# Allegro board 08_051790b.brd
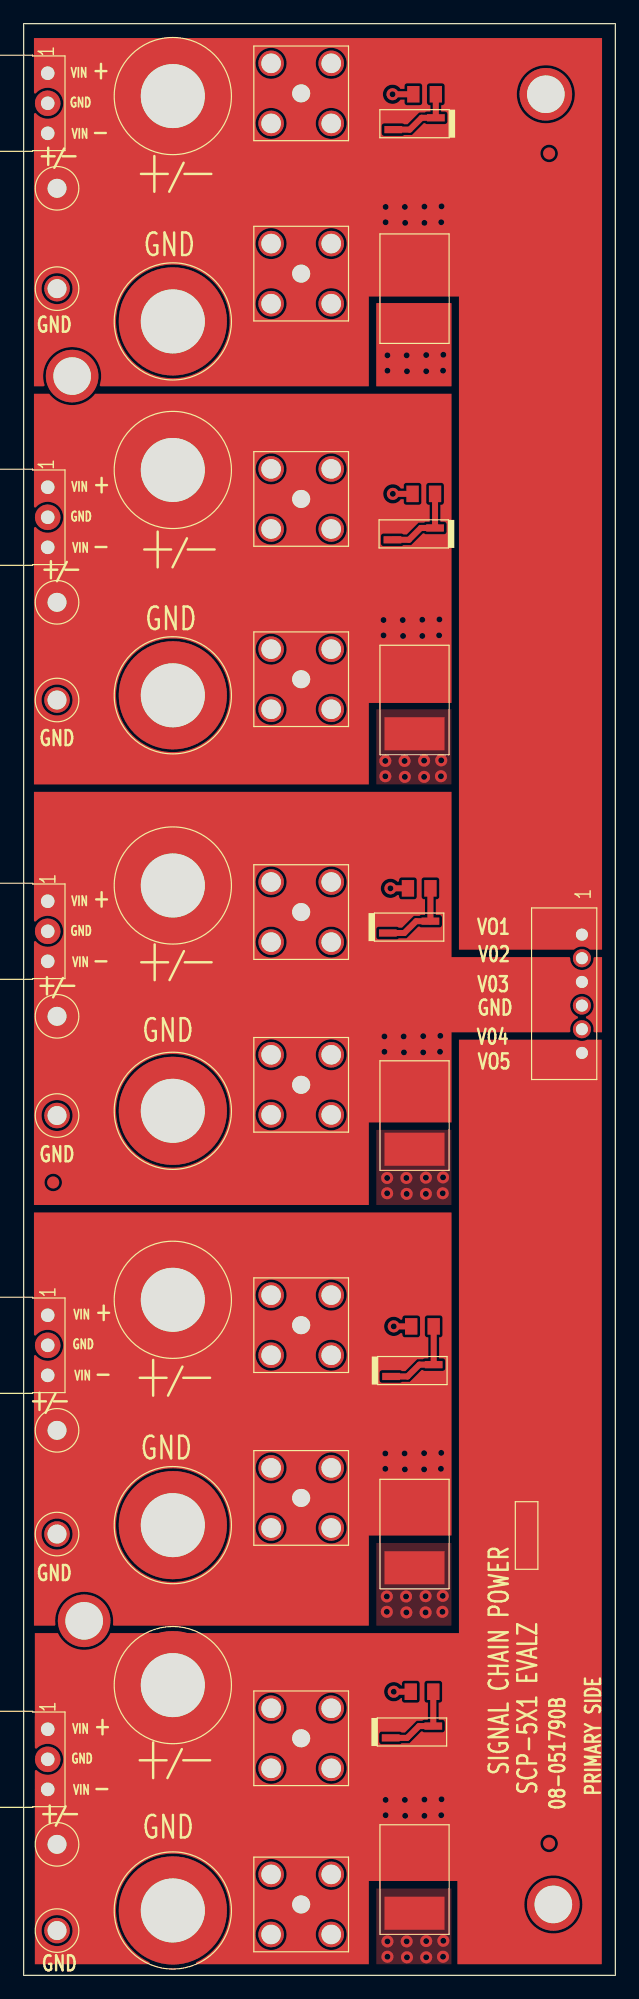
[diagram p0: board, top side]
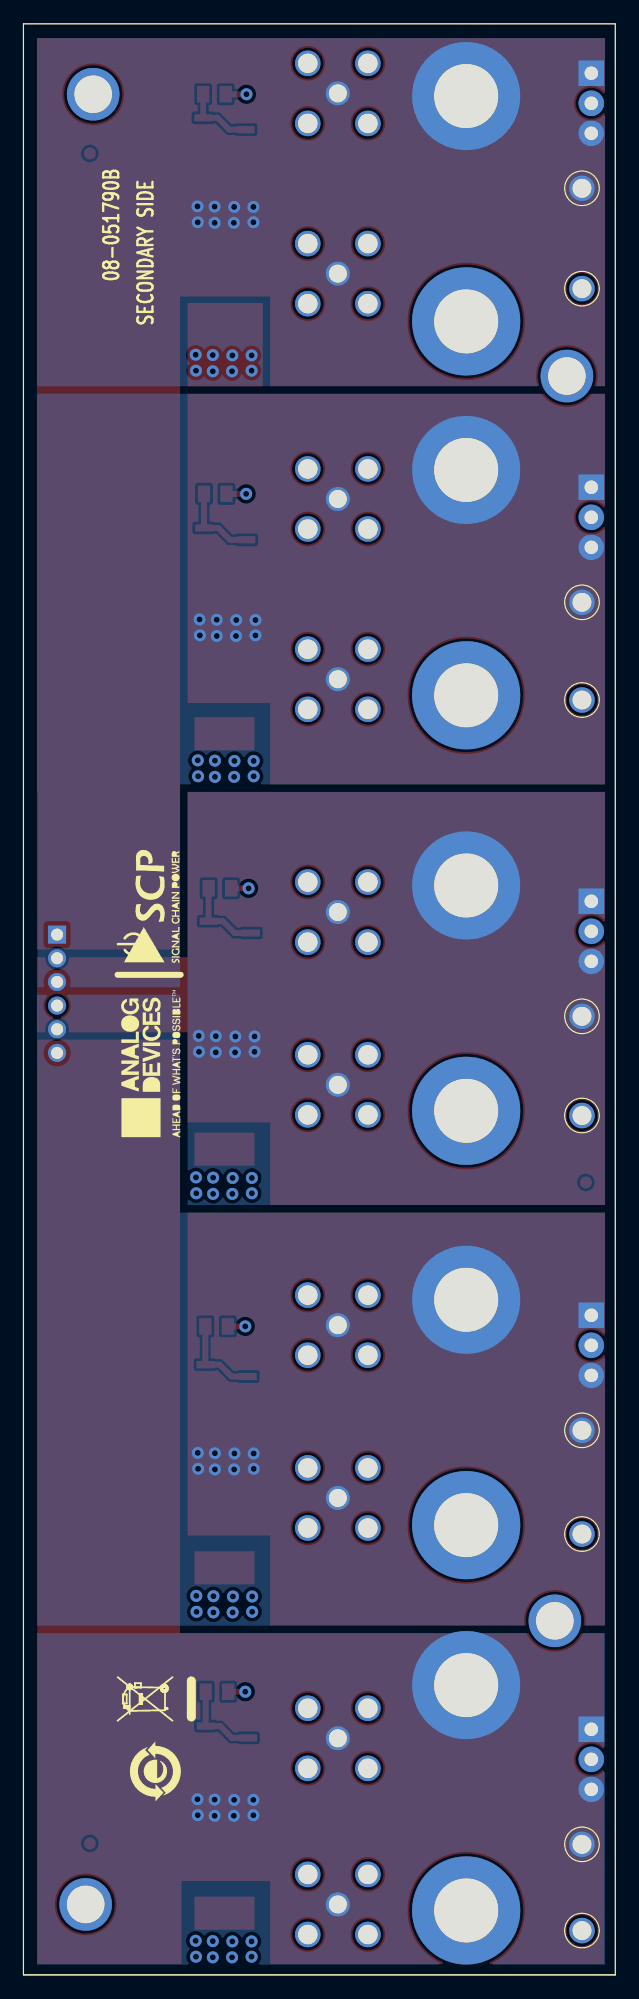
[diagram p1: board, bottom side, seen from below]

Outline 50 x 165 mm; copper layers: TOP, L2_GND, L3_GND, BOTTOM. Coordinates in mm from the lower left corner of the outline.
Outline path: 0,165 0,0 50,0 50,165 0,165

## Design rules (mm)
constraint set DEFAULT: min track width 0.203

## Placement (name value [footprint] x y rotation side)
C1  10UF  [C2220-1]  33.03 142.6 270 top
C2  10UF  [C2220-1]  33.03 107.82 270 top
C3  10UF  [C2220-1]  33.03 72.69 270 top
C4  10UF  [C2220-1]  33.03 37.31 270 top
C5  10UF  [C2220-1]  33.03 8.1 270 top
INPUT1  PBC03SBAN  [CNTHMHDRRA1X3L300W100H145]  2.03 160.81 270 top
INPUT2  PBC03SBAN  [CNTHMHDRRA1X3L300W100H145]  2.03 125.81 270 top
INPUT3  PBC03SBAN  [CNTHMHDRRA1X3L300W100H145]  2.03 90.81 270 top
INPUT4  PBC03SBAN  [CNTHMHDRRA1X3L300W100H145]  2.03 55.8 270 top
INPUT5  PBC03SBAN  [CNTHMHDRRA1X3L300W100H145]  2.03 20.8 270 top
J1  575-4  [CNBANANAD312LD203]  12.6 158.88 0 top
J2  575-4  [CNBANANAD312LD203]  12.6 139.83 0 top
J3  575-4  [CNBANANAD312LD203]  12.6 127.27 0 top
J4  575-4  [CNBANANAD312LD203]  12.6 108.22 0 top
J5  575-4  [CNBANANAD312LD203]  12.6 92.14 0 top
J6  575-4  [CNBANANAD312LD203]  12.6 73.09 0 top
J7  575-4  [CNBANANAD312LD203]  12.6 57.11 0 top
J8  575-4  [CNBANANAD312LD203]  12.6 38.06 0 top
J9  575-4  [CNBANANAD312LD203]  12.6 24.54 0 top
J10  575-4  [CNBANANAD312LD203]  12.6 5.49 0 top
LED1  LTST-C235KGKRKT  [LED1206_4P]  33.03 156.54 180 top
LED2  LTST-C235KGKRKT  [LED1206_4P]  32.96 121.86 180 top
LED3  LTST-C235KGKRKT  [LED1206_4P]  32.57 88.62 0 top
LED4  LTST-C235KGKRKT  [LED1206_4P]  32.85 51.13 0 top
LED5  LTST-C235KGKRKT  [LED1206_4P]  32.82 20.57 0 top
NOREF  -  []  0 165 0 top
NOREF#2  -  []  0 164.97 270 top
NOREF#3  -  [unnamed#2]  44.13 159.03 0 top
NOREF#4  -  []  0 165 0 top
NOREF#5  -  []  2.03 160.81 0 top
NOREF#6  -  [unnamed#2]  44.41 154.03 0 top
NOREF#7  -  [unnamed#2]  44.76 5.99 0 top
NOREF#8  -  []  -116.1 331.09 0 top
NOREF#9  -  []  0 0.02 0 top
NOREF#10  -  []  0 0 0 top
NOREF#11  -  []  50 165 0 top
NOREF#12  -  []  50 164.97 180 top
NOREF#13  -  []  -248.05 234.9 0 top
NOREF#14  -  []  130.27 193.05 0 top
NOREF#15  -  []  -172 -51.33 0 top
NOREF#16  -  []  25.59 187.4 0 top
NOREF#17  -  [unnamed#2]  44.41 11.15 0 top
NOREF#18  -  []  50 0 90 top
NOREF#19  -  []  -137.33 279.5 0 top
NOREF#20  -  []  2.03 160.81 0 top
NOREF#21  -  [unnamed#2]  2.5 67.03 0 top
NOREF#22  -  []  50 0.03 90 top
NOREF#23  -  []  0 0 0 top
NOREF#24  -  []  0 0 0 top
NOREF#25  -  []  -172.76 -53.49 0 top
NOREF#26  -  [unnamed#2]  5.11 29.97 0 top
NOREF#27  -  []  -111.58 106.27 0 top
NOREF#28  -  [unnamed#2]  4.1 135.2 0 top
NOREF#29  -  []  -170.61 -51.97 0 top
NOREF#30  -  []  38.87 17.25 90 bottom
NOREF#31  -  []  -27.91 92.79 90 bottom
NOREF#32  -  []  35.52 23.17 90 bottom
NOREF#33  -  []  -28.21 79.04 90 bottom
NOREF#34  -  []  39.23 76.77 90 bottom
NOREF#35  -  []  39.48 90.4 90 bottom
P6  DF3A-6P-2DSA  [CNTHMHDR1X6L551W197H209]  47.18 87.99 270 top
R1  TBD0805  [R0805]  33.88 159.03 180 top
R2  TBD0805  [R0805]  33.81 125.25 180 top
R3  TBD0805  [R0805]  33.42 91.9 180 top
R4  TBD0805  [R0805]  33.7 54.86 180 top
R5  TBD0805  [R0805]  33.67 23.98 180 top
SMA1  5-1814832-1  [CNTYCO1814832]  23.45 159.11 0 top
SMA2  5-1814832-1  [CNTYCO1814832]  23.45 143.87 0 top
SMA3  5-1814832-1  [CNTYCO1814832]  23.45 124.82 0 top
SMA4  5-1814832-1  [CNTYCO1814832]  23.45 109.58 0 top
SMA5  5-1814832-1  [CNTYCO1814832]  23.45 89.89 0 top
SMA6  5-1814832-1  [CNTYCO1814832]  23.45 75.29 0 top
SMA7  5-1814832-1  [CNTYCO1814832]  23.45 54.97 0 top
SMA8  5-1814832-1  [CNTYCO1814832]  23.45 40.36 0 top
SMA9  5-1814832-1  [CNTYCO1814832]  23.45 20.04 0 top
SMA10  5-1814832-1  [CNTYCO1814832]  23.45 5.99 0 top
TP1  RED  [CNKEY5XXXTP]  2.82 151.08 0 top
TP2  BLK  [CNKEY5XXXTP]  2.82 142.6 0 top
TP3  RED  [CNKEY5XXXTP]  2.82 116.08 0 top
TP4  BLK  [CNKEY5XXXTP]  2.82 107.82 0 top
TP5  RED  [CNKEY5XXXTP]  2.82 81.08 0 top
TP6  BLK  [CNKEY5XXXTP]  2.82 72.69 0 top
TP7  RED  [CNKEY5XXXTP]  2.82 46.08 0 top
TP8  BLK  [CNKEY5XXXTP]  2.82 37.31 0 top
TP9  RED  [CNKEY5XXXTP]  2.82 11.07 0 top
TP10  BLK  [CNKEY5XXXTP]  2.82 3.78 0 top

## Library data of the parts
C1-C5 = CAP: Tolerance: 10; User Part Number: UPN; alternate symbols: (); part number: CAP_SM-10UF,50V,10,E007065,C2220-1; tolerance: 10
INPUT1-INPUT5 = CN3P: Tolerance: N/A; User Part Number: UPN; alternate symbols: (CNTHMHDRRA1X3L300W100H145_SCP); part number: CN3P_TH-PBC03SBAN,E034137,CNTHMHDRRA1X3L300W100H145; tolerance: N/A
J1-J10 = CNTP1P: Tolerance: N/A; User Part Number: UPN; alternate symbols: (); part number: CNTP1P_TH-575-4,E012555,CNBANANAD312LD203; tolerance: N/A
LED1-LED5 = DIOLED_4P_V21: User Part Number: UPN; Tolerance: N/A; alternate symbols: (LED1206_4P_67BRDTHK); part number: DIOLED_4P_V21_SM-LTST-C235KGKRKT,2V,N/A,E034174,LED1206_4P; tolerance: N/A
P6 = CN6P: User Part Number: UPN; Tolerance: N/A; alternate symbols: (); part number: CN6P_TH-DF3A-6P-2DSA,E033743,CNTHMHDR1X6L551W197H209; tolerance: N/A
R1-R5 = RES: User Part Number: UPN; alternate symbols: (R0805L); part number: RES_SM-TBD0805,E004051,TBD0805,TBD0805,R0805
SMA1-SMA10 = CNBNC5P: Tolerance: N/A; User Part Number: UPN; alternate symbols: (); part number: CNBNC5P_TH-5-1814832-1,E010606,CNTYCO1814832; tolerance: N/A
TP1 TP3 TP5 TP7 TP9 = CNTP1P: Tolerance: N/A; User Part Number: UPN; alternate symbols: (); part number: CNTP1P_TH-RED,E023025,CNKEY5XXXTP; tolerance: N/A
TP2 TP4 TP6 TP8 TP10 = CNTP1P: Tolerance: N/A; User Part Number: UPN; alternate symbols: (); part number: CNTP1P_TH-BLK,E022843,CNKEY5XXXTP; tolerance: N/A

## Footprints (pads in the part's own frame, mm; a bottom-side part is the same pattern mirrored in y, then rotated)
C2220-1
  rect 2.794x5.08 smd: 1(-2.85,0) 2(2.85,0)
CNBANANAD312LD203
  round 9.144 hole 5.41: 1(0,0)
CNKEY5XXXTP
  round 2.159 hole 1.6: 1(0,0)
CNTHMHDR1X6L551W197H209
  rect 1.524x1.524 hole 1.016: 1(0,0)
  round 1.524 hole 1.016: 2(2,0) 3(4,0) 4(6,0) 5(8,0) 6(10,0)
CNTHMHDRRA1X3L300W100H145
  rect 2.159x2.159 hole 1.143: 1(0,0)
  round 2.159 hole 1.143: 2(2.54,0) 3(5.08,0)
CNTYCO1814832
  round 2.032 hole 1.524: 1(0,0)
  round 2.159 hole 1.651: 2(-2.54,2.54) 3(2.54,2.54) 4(2.54,-2.54) 5(-2.54,-2.54)
LED1206_4P
  rect 1.499x0.61 smd: 1(-1.8,-0.5) 2(1.8,-0.5) 3(1.8,0.5) 4(-1.8,0.5)
R0805
  rect 1.041x1.397 smd: 1(-0.95,0) 2(0.95,0)
unnamed#2
  round 4.445 hole 3.175 unplated: (0,0)

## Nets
AGND: C1.2(N2) C2.2(N2) C3.2(N2) C4.2(N2) C5.2(N2) INPUT1.2 INPUT2.2 INPUT3.2 INPUT4.2 INPUT5.2 J2.1(N1) J4.1(N1) J6.1(N1) J8.1(N1) J10.1(N1) P6.4 R1.2(N2) R2.2(N2) R3.2(N2) R4.2(N2) R5.2(N2) SMA1.2 SMA1.3 SMA1.4 SMA1.5(SH4) SMA2.2 SMA2.3 SMA2.4 SMA2.5(SH4) SMA3.2 SMA3.3 SMA3.4 SMA3.5(SH4) SMA4.2 SMA4.3 SMA4.4 SMA4.5(SH4) SMA5.2 SMA5.3 SMA5.4 SMA5.5(SH4) SMA6.2 SMA6.3 SMA6.4 SMA6.5(SH4) SMA7.2 SMA7.3 SMA7.4 SMA7.5(SH4) SMA8.2 SMA8.3 SMA8.4 SMA8.5(SH4) SMA9.2 SMA9.3 SMA9.4 SMA9.5(SH4) SMA10.2 SMA10.3 SMA10.4 SMA10.5(SH4) TP2.1(N1) TP4.1(N1) TP6.1(N1) TP8.1(N1) TP10.1(N1)
OUTPUT1: C1.1 INPUT1.1 INPUT1.3(N3) J1.1(N1) LED1.2 LED1.4(C2) P6.1 SMA1.1 SMA2.1 TP1.1(N1)
OUTPUT2: C2.1 INPUT2.1 INPUT2.3(N3) J3.1(N1) LED2.2 LED2.4(C2) P6.2 SMA3.1 SMA4.1 TP3.1(N1)
OUTPUT3: C3.1 INPUT3.1 INPUT3.3(N3) J5.1(N1) LED3.2 LED3.4(C2) P6.3 SMA5.1 SMA6.1 TP5.1(N1)
OUTPUT4: C4.1 INPUT4.1 INPUT4.3(N3) J7.1(N1) LED4.2 LED4.4(C2) P6.5 SMA7.1 SMA8.1 TP7.1(N1)
OUTPUT5: C5.1 INPUT5.1 INPUT5.3(N3) J9.1(N1) LED5.2 LED5.4(C2) P6.6(N6) SMA9.1 SMA10.1 TP9.1(N1)
UNNAMED_2_DIOLED4PV21_I36_A2: LED5.1 LED5.3 R5.1
UNNAMED_2_DIOLED4PV21_I37_A2: LED4.1 LED4.3 R4.1
UNNAMED_2_DIOLED4PV21_I54_A2: LED2.1 LED2.3 R2.1
UNNAMED_2_DIOLED4PV21_I55_A2: LED1.1 LED1.3 R1.1
UNNAMED_2_DIOLED4PV21_I57_A2: LED3.1 LED3.3 R3.1

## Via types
v1: diameter 1.016, hole 0.508, TOP to BOTTOM, 85 vias

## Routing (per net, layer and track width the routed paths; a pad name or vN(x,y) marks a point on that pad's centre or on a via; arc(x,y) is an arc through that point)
AGND: length 7.8
  TOP w0.508: R3.2 v1(30.99,91.9) ; R2.2 v1(31.2,125.25) ; R5.2 v1(31.27,23.98) ; R4.2 v1(31.27,54.86) ; R1.2 v1(31.17,159.03)
  vias: v1(30.56,102.67) v1(30.56,101.37) v1(30.74,136.96) v1(30.74,135.66) v1(30.71,67.41) v1(30.71,66.12) v1(30.69,32.03) v1(30.69,30.73) v1(30.74,2.87) v1(30.74,1.57) v1(32.19,102.67) v1(32.21,101.32) v1(32.37,136.96) v1(32.34,67.41) v1(32.37,66.07) v1(32.32,32.03) v1(32.34,30.68) v1(32.37,2.87) v1(32.39,135.61) v1(32.39,1.52) v1(33.84,102.69) v1(33.84,101.32) v1(33.97,32.05) v1(33.97,30.68) v1(34.02,136.98) v1(34.02,135.61) v1(33.99,67.44) v1(33.99,66.07) v1(34.02,2.9) v1(34.02,1.52) v1(35.26,101.37) v1(35.29,102.72) v1(35.46,137.01) v1(35.44,135.66) v1(35.44,67.46) v1(35.41,66.12) v1(35.41,32.08) v1(35.39,30.73) v1(35.46,2.92) v1(35.44,1.57)
OUTPUT1:
  vias: v1(30.59,149.5) v1(30.59,148.21) v1(32.21,149.5) v1(32.24,148.16) v1(33.86,149.53) v1(33.86,148.16) v1(35.31,149.56) v1(35.29,148.21)
OUTPUT2: length 0
  vias: v1(30.41,114.58) v1(30.41,113.28) v1(32.04,114.58) v1(32.06,113.23) v1(33.69,114.6) v1(33.69,113.23) v1(35.13,114.63) v1(35.11,113.28)
OUTPUT3:
  vias: v1(30.49,79.38) v1(30.49,78.08) v1(32.11,79.38) v1(32.14,78.03) v1(33.76,79.4) v1(33.76,78.03) v1(35.21,79.43) v1(35.19,78.08)
OUTPUT4:
  vias: v1(30.56,44.12) v1(30.56,42.82) v1(32.19,44.12) v1(32.21,42.77) v1(33.84,44.15) v1(33.84,42.77) v1(35.26,42.82) v1(35.29,44.17)
OUTPUT5: length 2.9
  TOP w0.203: 21.04,28.14 22.46,28.14 23.48,27.13
  vias: v1(30.59,14.83) v1(30.59,13.54) v1(32.21,14.83) v1(32.24,13.49) v1(33.86,14.86) v1(33.86,13.49) v1(35.31,14.88) v1(35.29,13.54)
UNNAMED_2_DIOLED4PV21_I36_A2: length 6.9
  TOP w0.508: LED5.1 32.41,20.07 33.41,21.07 LED5.3 R5.1
UNNAMED_2_DIOLED4PV21_I37_A2: length 7.2
  TOP w0.508: R4.1 LED4.3 33.44,51.63 32.44,50.63 LED4.1
UNNAMED_2_DIOLED4PV21_I54_A2: length 6.9
  TOP w0.508: R2.1 LED2.1 33.56,122.36 32.56,121.36 LED2.3
UNNAMED_2_DIOLED4PV21_I55_A2: length 6
  TOP w0.508: R1.1 LED1.1 33.62,157.04 32.62,156.04 LED1.3
UNNAMED_2_DIOLED4PV21_I57_A2: length 6.8
  TOP w0.508: R3.1 LED3.3 33.17,89.12 32.17,88.12 LED3.1

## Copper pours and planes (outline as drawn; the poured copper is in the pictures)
AGND on TOP (solid shape): 36.15,134.34 29.8,134.34 29.8,141.38 36.15,141.38
AGND on TOP: 29.8,71.48 29.8,65.13 36.15,65.13 36.15,71.48
AGND on TOP: 29.8,107.04 29.8,100.69 36.15,100.69 36.15,107.04
AGND on TOP: 29.8,7.34 29.8,0.94 36.15,0.94 36.15,7.34
AGND on TOP: 29.8,36.55 29.8,29.57 36.15,29.57 36.15,36.55
AGND on L2_GND: 0.87,64.49 36.15,64.49 36.15,32.74 29.9,32.74 29.9,29.57 0.87,29.57
AGND on L2_GND: 0.87,163.78 48.88,163.78 48.88,86.51 48.85,86.51 48.85,86.28 48.88,86.28 48.88,79.68 48.85,79.68 48.85,0.94 0.95,0.94 0.95,28.93 36.79,28.93 36.79,79.1 41.23,79.1 41.23,79.73 29.8,79.73 29.8,77.19 36.15,77.19 36.15,65.13 0.87,65.13 0.87,100.05 36.15,100.05 36.15,86.08 41.23,86.08 41.23,86.72 36.79,86.72 36.79,134.34 0.87,134.34
AGND on L2_GND: 0.87,133.71 36.15,133.71 36.15,103.86 29.8,103.86 29.8,100.69 0.87,100.69
AGND on L3_GND: 48.83,133.71 48.83,133.68 48.88,133.68 48.88,100 48.83,100 48.83,91.06 48.88,91.06 48.88,29.57 0.87,29.57 0.87,64.49 36.79,64.49 36.79,82.91 41.23,82.91 41.23,83.54 36.79,83.54 36.79,100.69 0.87,100.69 0.87,133.71
AGND on L3_GND: 0.87,28.93 48.88,28.93 48.88,0.9 36.4,0.9 36.4,3.91 29.9,3.91 29.9,0.9 0.87,0.9
AGND on L3_GND: 0.87,100.05 36.15,100.05 36.15,68.53 29.62,68.53 29.62,65.13 0.87,65.13
AGND on L3_GND: 0.87,163.78 48.88,163.78 48.88,134.34 36.79,134.34 36.79,137.9 29.39,137.9 29.39,134.34 0.87,134.34
(no net) on TOP: 0.87,64.49 36.15,64.49 36.15,37.19 29.17,37.19 29.17,29.57 0.87,29.57
(no net) on TOP: 29.8,141.38 29.8,134.34 36.15,134.34 36.15,141.38
(no net) on TOP: 0.87,163.78 48.88,163.78 48.88,86.72 36.79,86.72 36.79,141.94 29.17,141.94 29.17,134.34 0.87,134.34
(no net) on TOP: 0.87,100.05 36.15,100.05 36.15,86.08 48.88,86.08 48.88,79.73 36.15,79.73 36.15,72.11 29.17,72.11 29.17,65.13 0.87,65.13
(no net) on TOP: 0.95,28.93 36.79,28.93 36.79,79.1 48.85,79.1 48.85,0.94 36.66,0.94 36.66,7.98 29.17,7.98 29.17,0.94 0.95,0.94
(no net) on TOP: 0.87,133.71 36.15,133.71 36.15,107.57 29.17,107.57 29.17,100.69 0.87,100.69
OUTPUT1 on TOP (solid shape): outline of 1469 points within 0.87,86.72 48.88,163.78
OUTPUT1 on BOTTOM: 0.87,163.78 48.88,163.78 48.88,134.34 0.87,134.34
OUTPUT2 on TOP (solid shape): outline of 1230 points within 0.87,100.69 36.15,133.71
OUTPUT2 on BOTTOM: 48.83,133.71 48.83,133.68 48.88,133.68 48.88,100 48.83,100 48.83,83.54 36.79,83.54 36.79,100.69 0.87,100.69 0.87,133.71
OUTPUT3 on TOP (solid shape): outline of 1434 points within 0.87,65.13 48.88,100.05
OUTPUT3 on BOTTOM: 0.87,100.05 36.15,100.05 36.15,65.13 0.87,65.13
OUTPUT4 on TOP (solid shape): outline of 1275 points within 0.87,29.57 36.15,64.49
OUTPUT4 on BOTTOM: 36.79,82.91 48.88,82.91 48.88,29.57 0.87,29.57 0.87,64.49 36.79,64.49
OUTPUT5 on TOP (solid shape): outline of 1418 points within 0.95,0.94 48.85,79.1
OUTPUT5 on BOTTOM: 0.87,28.93 48.88,28.93 48.88,0.9 0.87,0.9

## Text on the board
User.Comments: CR_UNNAMED_5 | CR_UNNAMED_3 | CR_UNNAMED_2 | CR_UNNAMED_1 | CR_BLOK_4 | PRIMARY SIDE
Ref Des/Silkscreen Top: VIN | GND | / | V04 | V03 | VO1 | V02 | VO5 | 08-051790B | PRIMARY SIDE | - | + | SIGNAL CHAIN POWER | +-
PAGE_OUTLINE: 18DEC18 | B | AS PER ECR-086425 | 07MAY19 | J VIERNES | EVALZ
DIMENSION: (REF) | SEE FAB NOTE 15 | DIA MAX
User.15: 15.    THRU VIAS TO BE FILLED WITH SOLDERMASK.
User.17: L2 GND | 08-      -07
User.18: L3 GND | 08-      -08
User.45: FIGURE | SIZE | 20.0 | 40.0 | 45.0 | 60.0 | 63.0 | 65.0 | 213.0 | 125.0 | PLATED | NON-PLATED | FINISHED HOLES IN MILS | ALL UNITS ARE IN MILS | QTY | 85 | 6 | 15 | 10 | 40 | 4 | TOLERANCE/NOTES
